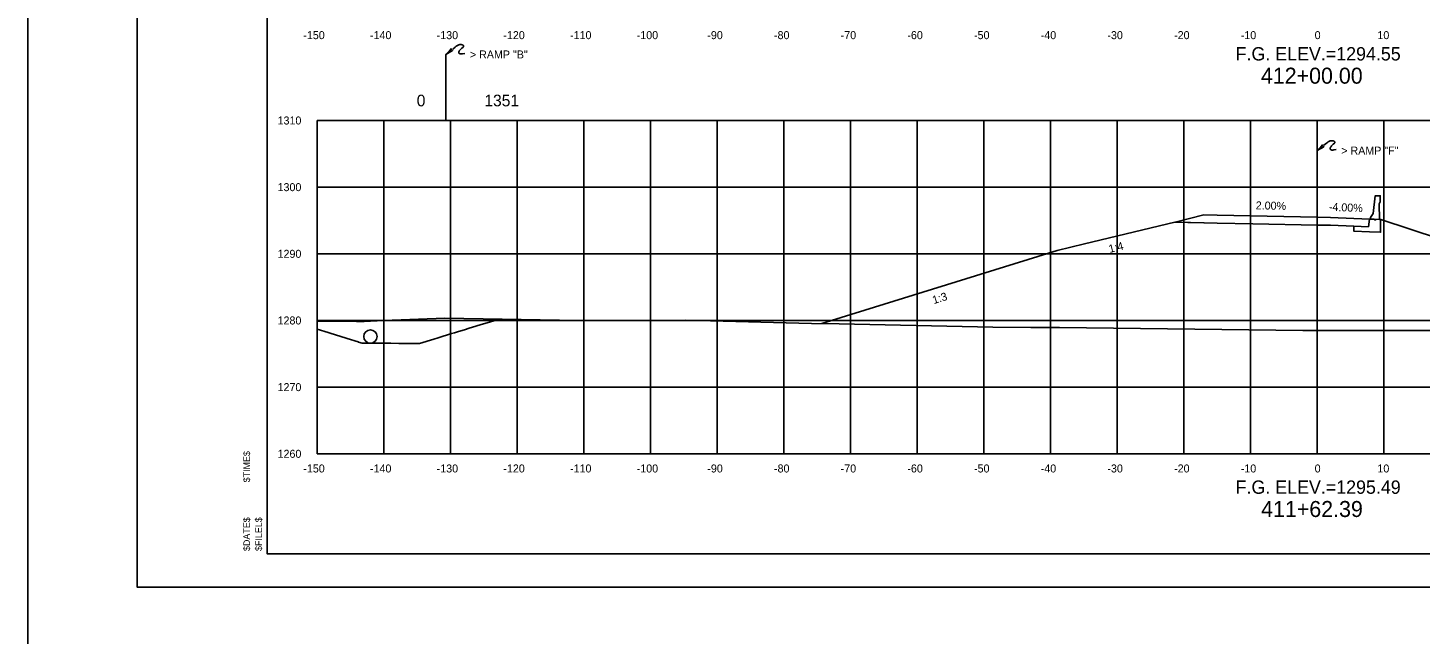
# Model space of a CAD drawing. Extents: x 2148105 to 2149976, y 144169 to 149705.
# Drawn here: x 2148219.9 to 2148428.8, y 145629.9 to 145720.8 of the extents above; entities that cross this region are included whole.
import ezdxf

# ---------------------------------------------------------------- set-up
doc = ezdxf.new("R2010")
doc.units = 0
for name, color, linetype in [('Bridge M-Header', 7, 'Continuous'), ('Default', 7, 'Continuous'), ('INR_Tracking', 7, 'Continuous'), ('PH1a-PR-DividingStrip', 7, 'Continuous'), ('PH1a-PR-Drives', 7, 'Continuous'), ('PH1a-PR-ServRd', 7, 'Continuous'), ('PH1a-RampM-Shld', 7, 'Continuous'), ('PH2-PR-Barrier', 7, 'Continuous'), ('PR-Dividing Strip', 7, 'Continuous'), ('PR_Align_PC', 7, 'Continuous'), ('PR_Align_Ramp_E', 7, 'Continuous'), ('PR_Align_Ramp_J', 7, 'Continuous'), ('PR_Storm_Channel', 7, 'Continuous'), ('PR_Storm_Conc_Box_PH1B', 7, 'Continuous'), ('PR_Storm_Conc_Pipe', 7, 'Continuous'), ('PR_Storm_Conc_Pipe_PH1B', 7, 'Continuous'), ('PR_Storm_Inlet_CICI_PH1A', 7, 'Continuous'), ('PR_Storm_Inlet_CICI_PH1B', 7, 'Continuous'), ('PR_Storm_Junction_Box_PH1B', 7, 'Continuous'), ('PR_Storm_MH_PH1B', 7, 'Continuous'), ('PR_Storm_Standard_Median_Drain_PH1B', 7, 'Continuous'), ('TopCut', 7, 'Continuous')]:
    doc.layers.add(name, color=color, linetype=linetype)

# ---------------------------------------------------------------- blocks, each defined once
blk = doc.blocks.new('POINT_DISPLAY')
at = {"layer": 'Default'}
blk.add_line((0, 0), (0, 0), dxfattribs=at)

msp = doc.modelspace()

# ---------------------------------------------------------------- linework, layer by layer
at = {"layer": 'INR_Tracking'}
msp.add_lwpolyline([(2148339, 145676.44), (2148339, 145676.44), (2148374.32, 145687.42), (2148378.4, 145688.39), (2148391.98, 145691.65), (2148392, 145691.66), (2148393.89, 145691.62), (2148394.33, 145691.61), (2148396.32, 145691.57), (2148396.32, 145691.57), (2148398.32, 145691.53), (2148398.33, 145691.53), (2148403.64, 145691.42), (2148413.32, 145691.23), (2148413.82, 145691.22), (2148415.32, 145691.19), (2148418.81, 145691.05), (2148418.82, 145691.05), (2148418.83, 145690.3), (2148421.15, 145690.21), (2148421.15, 145690.21), (2148422.8, 145690.14), (2148422.81, 145690.14), (2148422.82, 145690.89), (2148422.82, 145691.57), (2148422.83, 145692.06), (2148422.84, 145692.05), (2148431.66, 145689.18)], dxfattribs=at)
at = {"layer": 'PH1a-PR-ServRd'}
msp.add_lwpolyline([(2148570.82, 145641.91), (2148255.82, 145641.91), (2148255.82, 145851.91), (2148570.82, 145851.91)], close=True, dxfattribs=at)
at = {"layer": 'PH1a-RampM-Shld'}
msp.add_circle((2148271.32, 145674.5), 1, dxfattribs=at)
at = {"layer": 'PH2-PR-Barrier'}
msp.add_line((2148413.32, 145692.4), (2148413.32, 145702.4), dxfattribs=at)
for points in [[(2148413.32, 145702.4), (2148413.84, 145702.95), (2148414.1, 145703.25), (2148414.18, 145703.09), (2148414.32, 145702.97), (2148413.32, 145702.4)], [(2148414.33, 145703.21), (2148414.69, 145703.5), (2148414.85, 145703.63), (2148414.94, 145703.7), (2148415.04, 145703.76), (2148415.14, 145703.81), (2148415.26, 145703.84), (2148415.39, 145703.87), (2148415.49, 145703.88), (2148415.57, 145703.88), (2148415.65, 145703.88), (2148415.72, 145703.86), (2148415.78, 145703.85), (2148415.83, 145703.83), (2148415.87, 145703.8), (2148415.91, 145703.77), (2148415.95, 145703.73), (2148415.98, 145703.67), (2148415.97, 145703.61), (2148415.96, 145703.57), (2148415.91, 145703.5), (2148415.72, 145703.34), (2148415.53, 145703.18), (2148415.46, 145703.1), (2148415.39, 145703.03), (2148415.33, 145702.93), (2148415.29, 145702.87), (2148415.25, 145702.78), (2148415.25, 145702.7), (2148415.27, 145702.62), (2148415.31, 145702.55), (2148415.36, 145702.52), (2148415.42, 145702.49), (2148415.53, 145702.48), (2148415.66, 145702.48), (2148415.82, 145702.5), (2148416.15, 145702.54)]]:
    msp.add_lwpolyline(points, dxfattribs=at)
at = {"layer": 'PR-Dividing Strip'}
msp.add_line((2148282.65, 145706.82), (2148282.65, 145716.82), dxfattribs=at)
for points in [[(2148282.65, 145716.82), (2148283.16, 145717.37), (2148283.42, 145717.68), (2148283.5, 145717.51), (2148283.65, 145717.39), (2148282.65, 145716.82)], [(2148283.66, 145717.63), (2148284.01, 145717.92), (2148284.17, 145718.05), (2148284.27, 145718.13), (2148284.37, 145718.18), (2148284.46, 145718.23), (2148284.58, 145718.27), (2148284.72, 145718.3), (2148284.81, 145718.3), (2148284.89, 145718.3), (2148284.98, 145718.3), (2148285.05, 145718.28), (2148285.1, 145718.27), (2148285.15, 145718.25), (2148285.2, 145718.22), (2148285.23, 145718.19), (2148285.27, 145718.15), (2148285.3, 145718.09), (2148285.3, 145718.03), (2148285.29, 145717.99), (2148285.23, 145717.92), (2148285.04, 145717.76), (2148284.86, 145717.6), (2148284.78, 145717.52), (2148284.72, 145717.45), (2148284.65, 145717.35), (2148284.62, 145717.29), (2148284.58, 145717.2), (2148284.57, 145717.13), (2148284.59, 145717.04), (2148284.63, 145716.97), (2148284.68, 145716.94), (2148284.74, 145716.92), (2148284.85, 145716.9), (2148284.98, 145716.91), (2148285.14, 145716.92), (2148285.48, 145716.96)]]:
    msp.add_lwpolyline(points, dxfattribs=at)
at = {"layer": 'PR_Align_Ramp_E'}
msp.add_lwpolyline([(2148219.95, 145865.16), (2148579.95, 145865.16), (2148579.95, 145625.16), (2148219.95, 145625.16)], close=True, dxfattribs=at)
at = {"layer": 'PR_Align_Ramp_J'}
msp.add_lwpolyline([(2148236.32, 145856.91), (2148576.32, 145856.91), (2148576.32, 145636.91), (2148236.32, 145636.91)], close=True, dxfattribs=at)
at = {"layer": 'PR_Storm_Channel'}
msp.add_lwpolyline([(2148392, 145691.66), (2148396.32, 145692.74), (2148398.32, 145692.7), (2148413.32, 145692.4), (2148415.32, 145692.36), (2148421.15, 145692.12)], dxfattribs=at)
at = {"layer": 'PR_Storm_Conc_Box_PH1B'}
for p, q in [((2148263.32, 145706.91), (2148563.32, 145706.91)), ((2148263.32, 145656.91), (2148263.32, 145706.91)), ((2148273.32, 145656.91), (2148273.32, 145706.91)), ((2148283.32, 145656.91), (2148283.32, 145706.91)), ((2148293.32, 145656.91), (2148293.32, 145706.91)), ((2148303.32, 145656.91), (2148303.32, 145706.91)), ((2148313.32, 145656.91), (2148313.32, 145706.91)), ((2148323.32, 145656.91), (2148323.32, 145706.91)), ((2148333.32, 145656.91), (2148333.32, 145706.91)), ((2148343.32, 145656.91), (2148343.32, 145706.91)), ((2148353.32, 145656.91), (2148353.32, 145706.91)), ((2148363.32, 145656.91), (2148363.32, 145706.91)), ((2148373.32, 145656.91), (2148373.32, 145706.91)), ((2148383.32, 145656.91), (2148383.32, 145706.91)), ((2148393.32, 145656.91), (2148393.32, 145706.91)), ((2148403.32, 145656.91), (2148403.32, 145706.91)), ((2148413.32, 145656.91), (2148413.32, 145706.91)), ((2148423.32, 145656.91), (2148423.32, 145706.91)), ((2148263.32, 145696.91), (2148563.32, 145696.91)), ((2148263.32, 145686.91), (2148563.32, 145686.91)), ((2148263.32, 145676.91), (2148563.32, 145676.91)), ((2148263.32, 145666.91), (2148563.32, 145666.91)), ((2148263.32, 145656.91), (2148563.32, 145656.91))]:
    msp.add_line(p, q, dxfattribs=at)
at = {"layer": 'PR_Storm_Conc_Pipe'}
msp.add_lwpolyline([(2148263.32, 145675.63), (2148264.97, 145675.11), (2148265.27, 145675.01), (2148267.69, 145674.25), (2148267.84, 145674.21), (2148269.5, 145673.69), (2148269.53, 145673.68), (2148270.07, 145673.51), (2148270.41, 145673.51), (2148270.93, 145673.5), (2148273, 145673.49), (2148274.38, 145673.49), (2148275.6, 145673.48), (2148277.5, 145673.47), (2148278.22, 145673.47), (2148278.68, 145673.47), (2148280.85, 145674.13), (2148281.46, 145674.31), (2148283.49, 145674.94), (2148283.95, 145675.08), (2148284.53, 145675.25), (2148285.44, 145675.53), (2148286.15, 145675.75), (2148288.29, 145676.4), (2148288.82, 145676.56), (2148290.68, 145677.13)], dxfattribs=at)
at = {"layer": 'PR_Storm_Conc_Pipe_PH1B'}
msp.add_lwpolyline([(2148255.82, 145641.91), (2148570.82, 145641.91), (2148570.82, 145851.91), (2148255.82, 145851.91)], close=True, dxfattribs=at)
msp.add_lwpolyline([(2148255.82, 145641.91), (2148570.82, 145641.91), (2148570.82, 145851.91), (2148255.82, 145851.91)], close=True, dxfattribs=at)
at = {"layer": 'PR_Storm_Inlet_CICI_PH1A'}
for points in [[(2148422.64, 145692.07), (2148422.63, 145694.43), (2148422.76, 145694.7), (2148422.76, 145695.62), (2148422.01, 145695.62), (2148421.73, 145692.95), (2148421.33, 145692.37), (2148421.32, 145692.12), (2148421.9, 145692.09), (2148421.9, 145692.01), (2148422.08, 145692), (2148422.08, 145692.09)], [(2148422.81, 145690.14), (2148421.15, 145690.21), (2148418.83, 145690.3), (2148418.82, 145691.05), (2148420.99, 145690.96), (2148421.15, 145692.12), (2148421.32, 145692.12), (2148421.9, 145692.09), (2148421.9, 145692.01), (2148422.08, 145692), (2148422.08, 145692.09), (2148422.64, 145692.07), (2148422.83, 145692.06), (2148422.82, 145690.89)]]:
    msp.add_lwpolyline(points, close=True, dxfattribs=at)
at = {"layer": 'PR_Storm_Inlet_CICI_PH1B'}
msp.add_lwpolyline([(2148263.32, 145676.82), (2148269.24, 145676.78), (2148270.4, 145676.78), (2148273.31, 145676.92), (2148282.47, 145677.28), (2148302.53, 145676.92), (2148305.85, 145676.92), (2148318.53, 145676.95), (2148337.48, 145676.47), (2148341.61, 145676.39), (2148364.67, 145675.93), (2148370.35, 145675.87), (2148374.68, 145675.86), (2148411.16, 145675.42), (2148412.43, 145675.4), (2148430.21, 145675.39)], dxfattribs=at)
at = {"layer": 'PR_Storm_Standard_Median_Drain_PH1B'}
for q in [(2148263.32, 145706.91), (2148563.32, 145656.91)]:
    msp.add_line((2148263.32, 145656.91), q, dxfattribs=at)
at = {"layer": 'TopCut'}
msp.add_lwpolyline([(2148431.66, 145689.18), (2148422.84, 145692.05), (2148422.83, 145692.06), (2148422.82, 145691.57), (2148422.82, 145690.89), (2148422.81, 145690.14), (2148422.8, 145690.14), (2148421.15, 145690.21), (2148421.15, 145690.21), (2148418.83, 145690.3), (2148418.82, 145691.05), (2148418.81, 145691.05), (2148415.32, 145691.19), (2148413.82, 145691.22), (2148413.32, 145691.23), (2148403.64, 145691.42), (2148398.33, 145691.53), (2148398.32, 145691.53), (2148396.32, 145691.57), (2148396.32, 145691.57), (2148394.33, 145691.61), (2148393.89, 145691.62), (2148392, 145691.66), (2148391.98, 145691.65), (2148378.4, 145688.39), (2148374.32, 145687.42), (2148339, 145676.44), (2148339, 145676.44), (2148339, 145676.44), (2148341.61, 145676.39), (2148364.67, 145675.93), (2148370.35, 145675.87), (2148374.68, 145675.86), (2148411.16, 145675.42), (2148412.43, 145675.4), (2148430.21, 145675.39)], dxfattribs=at)

# ---------------------------------------------------------------- block references
at = {"layer": 'PR_Storm_Conc_Pipe_PH1B', "xscale": 10, "yscale": 10}
for p in [(2148398.32, 145692.7), (2148398.32, 145692.7), (2148415.32, 145692.36), (2148415.32, 145692.36), (2148421.15, 145692.12), (2148421.15, 145692.12)]:
    msp.add_blockref('POINT_DISPLAY', p, dxfattribs=at)

# ---------------------------------------------------------------- texts
at = {"layer": 'Bridge M-Header'}
for s, rotation, p in [('2.00%', 358.8542, (2148404.09, 145693.58)), ('-4.00%', 357.7094, (2148415.04, 145693.37))]:
    msp.add_text(s, height=1.2, rotation=rotation, dxfattribs=at).set_placement(p)
at = {"layer": 'PH1a-PR-DividingStrip'}
for s, rotation, p in [('1:4', 13.4853, (2148382.19, 145687.04)), ('1:3', 17.2684, (2148355.81, 145679.36))]:
    msp.add_text(s, height=1.2, rotation=rotation, dxfattribs=at).set_placement(p)
at = {"layer": 'PH1a-PR-Drives'}
for s, p in [('$TIME$', (2148253.27, 145652.63)), ('$DATE$', (2148253.27, 145642.33)), ('$FILEL$', (2148255.05, 145642.33))]:
    msp.add_text(s, height=1, rotation=90, dxfattribs=at).set_placement(p)
at = {"layer": 'PH2-PR-Barrier'}
msp.add_text('> RAMP "F"', height=1.2, rotation=360, dxfattribs=at).set_placement((2148416.92, 145701.79))
at = {"layer": 'PR-Dividing Strip'}
msp.add_text('> RAMP "B"', height=1.2, rotation=360, dxfattribs=at).set_placement((2148286.24, 145716.21))
at = {"layer": 'PR_Align_PC'}
for s, p in [('0', (2148278.27, 145709.03)), ('1351', (2148288.41, 145709.03))]:
    msp.add_text(s, height=1.75, dxfattribs=at).set_placement(p)
at = {"layer": 'PR_Storm_Junction_Box_PH1B'}
for s, p in [('412+00.00', (2148404.87, 145712.43)), ('411+62.39', (2148404.9, 145647.43))]:
    msp.add_text(s, height=2.4, dxfattribs=at).set_placement(p)
at = {"layer": 'PR_Storm_MH_PH1B'}
for s, height, p in [('-150', 1.2, (2148261.26, 145719.11)), ('-140', 1.2, (2148271.26, 145719.11)), ('-130', 1.2, (2148281.26, 145719.11)), ('-120', 1.2, (2148291.26, 145719.11)), ('-110', 1.2, (2148301.26, 145719.11)), ('-100', 1.2, (2148311.26, 145719.11)), ('-90', 1.2, (2148321.85, 145719.11)), ('-80', 1.2, (2148331.85, 145719.11)), ('-70', 1.2, (2148341.85, 145719.11)), ('-60', 1.2, (2148351.85, 145719.11)), ('-50', 1.2, (2148361.85, 145719.11)), ('-40', 1.2, (2148371.85, 145719.11)), ('-30', 1.2, (2148381.85, 145719.11)), ('-20', 1.2, (2148391.85, 145719.11)), ('-10', 1.2, (2148401.85, 145719.11)), ('0', 1.2, (2148412.93, 145719.11)), ('10', 1.2, (2148422.34, 145719.11)), ('F.G. ELEV.=1294.55', 2, (2148401.08, 145715.91)), ('1310', 1.2, (2148257.4, 145706.31)), ('1300', 1.2, (2148257.4, 145696.31)), ('1290', 1.2, (2148257.4, 145686.31)), ('1280', 1.2, (2148257.4, 145676.31)), ('1270', 1.2, (2148257.4, 145666.31)), ('1260', 1.2, (2148257.4, 145656.31)), ('-150', 1.2, (2148261.26, 145654.11)), ('-140', 1.2, (2148271.26, 145654.11)), ('-130', 1.2, (2148281.26, 145654.11)), ('-120', 1.2, (2148291.26, 145654.11)), ('-110', 1.2, (2148301.26, 145654.11)), ('-100', 1.2, (2148311.26, 145654.11)), ('-90', 1.2, (2148321.85, 145654.11)), ('-80', 1.2, (2148331.85, 145654.11)), ('-70', 1.2, (2148341.85, 145654.11)), ('-60', 1.2, (2148351.85, 145654.11)), ('-50', 1.2, (2148361.85, 145654.11)), ('-40', 1.2, (2148371.85, 145654.11)), ('-30', 1.2, (2148381.85, 145654.11)), ('-20', 1.2, (2148391.85, 145654.11)), ('-10', 1.2, (2148401.85, 145654.11)), ('0', 1.2, (2148412.93, 145654.11)), ('10', 1.2, (2148422.34, 145654.11)), ('F.G. ELEV.=1295.49', 2, (2148401.08, 145650.91))]:
    msp.add_text(s, height=height, dxfattribs=at).set_placement(p)

doc.saveas('drawing.dxf')
